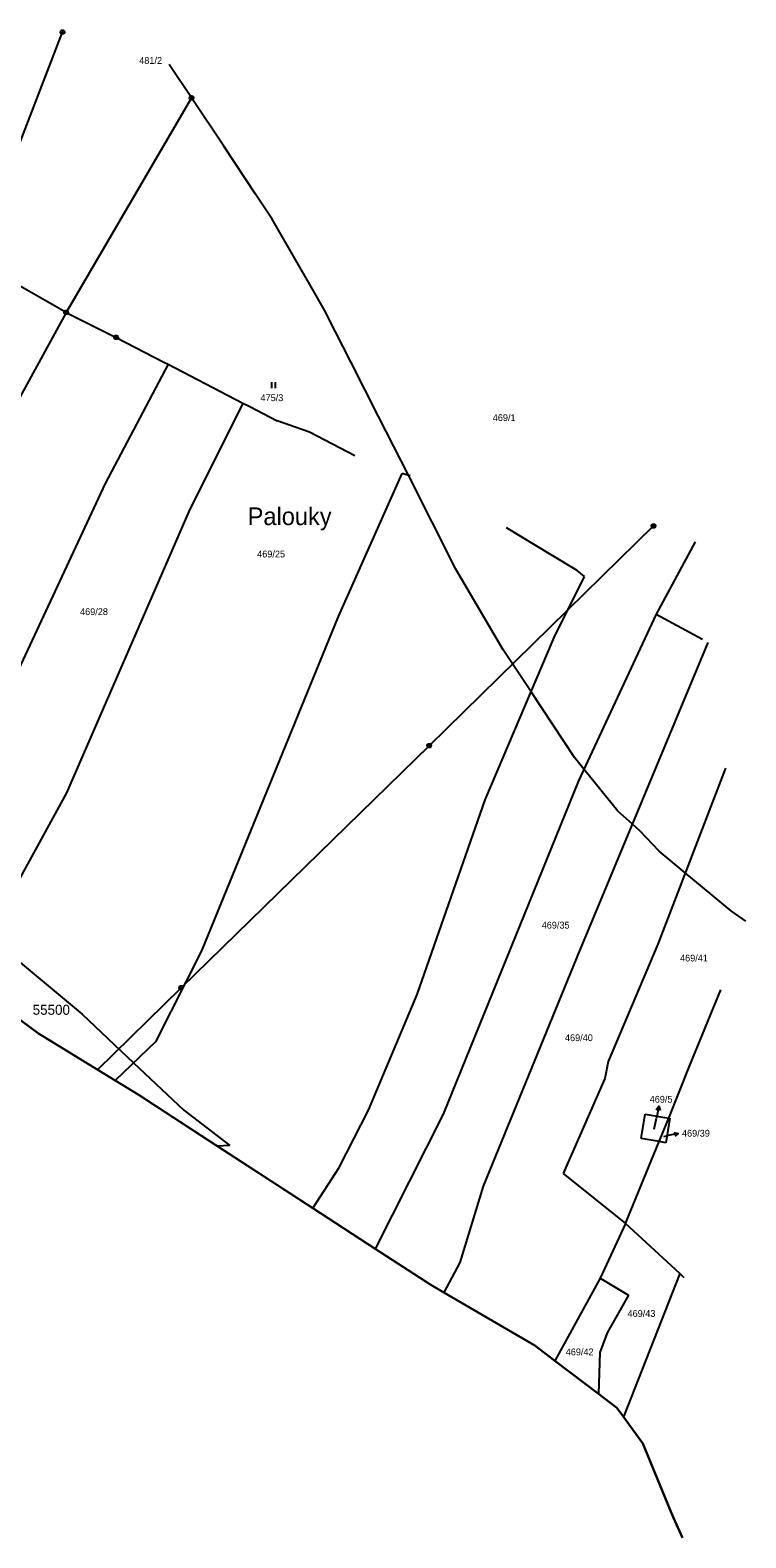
# Model space of a CAD drawing. Extents: x -755359 to -754474, y -1162585 to -1161655.
# Drawn here: x -754652.1 to -754473.6, y -1162087.8 to -1161711.6 of the extents above; entities that cross this region are included whole.
import ezdxf

# ---------------------------------------------------------------- set-up
doc = ezdxf.new("R2010")
doc.units = 0
for name, color, linetype in [('Vrstva 1', 7, 'Continuous'), ('Vrstva 11', 7, 'Continuous'), ('Vrstva 2', 7, 'Continuous'), ('Vrstva 3', 7, 'Continuous'), ('Vrstva 6', 7, 'Continuous'), ('Vrstva 7', 7, 'Continuous'), ('Vrstva 8', 7, 'Continuous')]:
    doc.layers.add(name, color=color, linetype=linetype)

msp = doc.modelspace()

# ---------------------------------------------------------------- linework, layer by layer
at = {"layer": 'Vrstva 1'}
for p, q in [((-754665.97, -1161769.03), (-754644.01, -1161712.08)), ((-754644.01, -1161712.08), (-754644.01, -1161712.08)), ((-754611.88, -1161728.5), (-754643.13, -1161782.03)), ((-754611.88, -1161728.5), (-754611.88, -1161728.5)), ((-754643.13, -1161782.03), (-754665.97, -1161769.03)), ((-754643.13, -1161782.03), (-754669.27, -1161829.84)), ((-754643.13, -1161782.03), (-754630.65, -1161788.28)), ((-754630.65, -1161788.28), (-754630.65, -1161788.28)), ((-754630.65, -1161788.28), (-754618.73, -1161794.45)), ((-754617.71, -1161794.98), (-754633.36, -1161824.71)), ((-754618.73, -1161794.45), (-754618.73, -1161794.45)), ((-754618.73, -1161794.45), (-754617.71, -1161794.98)), ((-754617.71, -1161794.98), (-754599.04, -1161804.66)), ((-754599.04, -1161804.66), (-754612.56, -1161831.72)), ((-754599.04, -1161804.66), (-754597.32, -1161805.55)), ((-754597.32, -1161805.55), (-754597.32, -1161805.55)), ((-754597.32, -1161805.55), (-754590.51, -1161809.08)), ((-754582.4, -1161811.93), (-754590.51, -1161809.08)), ((-754590.51, -1161809.08), (-754590.51, -1161809.08)), ((-754582.4, -1161811.93), (-754582.4, -1161811.93)), ((-754571.08, -1161817.79), (-754582.4, -1161811.93)), ((-754571.08, -1161817.79), (-754571.08, -1161817.79)), ((-754633.36, -1161824.71), (-754655.58, -1161872.43)), ((-754559.41, -1161822.27), (-754575.25, -1161857.88)), ((-754557.3, -1161822.8), (-754559.41, -1161822.27)), ((-754557.3, -1161822.8), (-754557.3, -1161822.8)), ((-754612.56, -1161831.72), (-754643, -1161901.95)), ((-754522.55, -1161842.29), (-754533.32, -1161835.8)), ((-754533.32, -1161835.8), (-754533.32, -1161835.8)), ((-754486.25, -1161839.25), (-754495.95, -1161857.32)), ((-754486.25, -1161839.25), (-754486.25, -1161839.25)), ((-754515.62, -1161846.48), (-754522.55, -1161842.29)), ((-754522.55, -1161842.29), (-754522.55, -1161842.29)), ((-754513.85, -1161847.95), (-754515.62, -1161846.48)), ((-754515.62, -1161846.48), (-754515.62, -1161846.48)), ((-754521.37, -1161863.15), (-754513.85, -1161847.95)), ((-754575.25, -1161857.88), (-754609.39, -1161941.34)), ((-754495.95, -1161857.32), (-754515.32, -1161898.89)), ((-754495.95, -1161857.32), (-754484.41, -1161863.55)), ((-754538.63, -1161903.69), (-754521.37, -1161863.15)), ((-754483.05, -1161864.39), (-754515.76, -1161942.9)), ((-754484.41, -1161863.55), (-754484.41, -1161863.55)), ((-754483.05, -1161864.39), (-754483.05, -1161864.39)), ((-754478.67, -1161895.77), (-754495.56, -1161939.67)), ((-754478.67, -1161895.77), (-754478.67, -1161895.77)), ((-754515.32, -1161898.89), (-754549.09, -1161982.12)), ((-754643, -1161901.95), (-754657.61, -1161928.54)), ((-754555.59, -1161952.23), (-754538.63, -1161903.69)), ((-754609.39, -1161941.34), (-754620.82, -1161964.09)), ((-754495.56, -1161939.67), (-754507.92, -1161969.01)), ((-754515.76, -1161942.9), (-754539.09, -1162000.11)), ((-754662.1, -1161953.11), (-754649.99, -1161962)), ((-754567.68, -1161981.15), (-754555.59, -1161952.23)), ((-754487.65, -1161970.13), (-754479.83, -1161951.12)), ((-754479.83, -1161951.12), (-754479.83, -1161951.12)), ((-754649.99, -1161962), (-754630.9, -1161973.72)), ((-754620.82, -1161964.09), (-754630.9, -1161973.72)), ((-754507.92, -1161969.01), (-754508.8, -1161973.21)), ((-754492.83, -1161983.08), (-754487.65, -1161970.13)), ((-754630.9, -1161973.72), (-754625.17, -1161977.24)), ((-754508.8, -1161973.21), (-754519.17, -1161996.94)), ((-754625.17, -1161977.24), (-754581.59, -1162005.57)), ((-754574.99, -1161995.43), (-754567.68, -1161981.15)), ((-754549.09, -1161982.12), (-754566.03, -1162015.68)), ((-754499.71, -1161988.2), (-754498.73, -1161982.13)), ((-754498.73, -1161982.13), (-754492.83, -1161983.08)), ((-754495.19, -1161988.97), (-754492.83, -1161983.08)), ((-754492.54, -1161983.13), (-754493.55, -1161989.25)), ((-754492.83, -1161983.08), (-754492.54, -1161983.13)), ((-754503.57, -1162009.41), (-754495.19, -1161988.97)), ((-754495.19, -1161988.97), (-754499.71, -1161988.2)), ((-754493.55, -1161989.25), (-754495.19, -1161988.97)), ((-754581.59, -1162005.57), (-754574.99, -1161995.43)), ((-754519.17, -1161996.94), (-754503.57, -1162009.41)), ((-754539.09, -1162000.11), (-754544.92, -1162019.1)), ((-754581.59, -1162005.57), (-754566.03, -1162015.68)), ((-754503.57, -1162009.41), (-754509.9, -1162023.04)), ((-754490.05, -1162021.88), (-754503.57, -1162009.41)), ((-754566.03, -1162015.68), (-754552.14, -1162024.71)), ((-754544.92, -1162019.1), (-754548.91, -1162026.6)), ((-754552.14, -1162024.71), (-754548.91, -1162026.6)), ((-754509.9, -1162023.04), (-754521.23, -1162043.66)), ((-754509.9, -1162023.04), (-754502.88, -1162027.26)), ((-754490.05, -1162021.88), (-754504.08, -1162057.68)), ((-754488.93, -1162022.92), (-754490.05, -1162021.88)), ((-754488.93, -1162022.92), (-754488.93, -1162022.92)), ((-754548.91, -1162026.6), (-754526.24, -1162039.85)), ((-754502.88, -1162027.26), (-754508.16, -1162036.68)), ((-754508.16, -1162036.68), (-754510.03, -1162041.56)), ((-754526.24, -1162039.85), (-754521.23, -1162043.66)), ((-754510.03, -1162041.56), (-754510.34, -1162051.93)), ((-754521.23, -1162043.66), (-754510.34, -1162051.93)), ((-754510.34, -1162051.93), (-754505.73, -1162055.42)), ((-754505.73, -1162055.42), (-754504.08, -1162057.68)), ((-754504.08, -1162057.68), (-754499.27, -1162064.28)), ((-754499.27, -1162064.28), (-754492.53, -1162080.68)), ((-754492.53, -1162080.68), (-754491.64, -1162082.85)), ((-754492.53, -1162080.68), (-754492.53, -1162080.68)), ((-754491.64, -1162082.85), (-754489.42, -1162087.84)), ((-754489.42, -1162087.84), (-754489.42, -1162087.84))]:
    msp.add_line(p, q, dxfattribs=at)
at = {"layer": 'Vrstva 11'}
for p, q in [((-754611.87, -1161728.48), (-754617.39, -1161720.16)), ((-754603.83, -1161740.58), (-754611.87, -1161728.48)), ((-754595.89, -1161752.54), (-754603.83, -1161740.58)), ((-754591.77, -1161758.73), (-754595.89, -1161752.54)), ((-754580.8, -1161777.83), (-754591.77, -1161758.73)), ((-754578.27, -1161782.24), (-754580.8, -1161777.83)), ((-754577.82, -1161783.11), (-754578.27, -1161782.24)), ((-754572.13, -1161794.35), (-754577.82, -1161783.11)), ((-754565.23, -1161807.97), (-754572.13, -1161794.35)), ((-754557.77, -1161822.68), (-754565.23, -1161807.97)), ((-754545.9, -1161846.11), (-754557.77, -1161822.68)), ((-754534.14, -1161866.25), (-754545.9, -1161846.11)), ((-754527.17, -1161876.76), (-754534.14, -1161866.25)), ((-754516.34, -1161893.09), (-754527.17, -1161876.76)), ((-754513.98, -1161896.01), (-754516.34, -1161893.09)), ((-754505.53, -1161906.48), (-754513.98, -1161896.01)), ((-754501.93, -1161909.7), (-754505.53, -1161906.48)), ((-754499.94, -1161911.48), (-754501.93, -1161909.7)), ((-754495.2, -1161916.49), (-754499.94, -1161911.48)), ((-754488.71, -1161921.88), (-754495.2, -1161916.49)), ((-754477.16, -1161931.47), (-754488.71, -1161921.88)), ((-754473.59, -1161933.93), (-754477.16, -1161931.47)), ((-754663.8, -1161936.61), (-754639.14, -1161957.17)), ((-754649.99, -1161962), (-754662.1, -1161953.11)), ((-754639.14, -1161957.17), (-754626.28, -1161969.31)), ((-754630.9, -1161973.72), (-754649.99, -1161962)), ((-754626.28, -1161969.31), (-754613.8, -1161981.1)), ((-754625.17, -1161977.24), (-754630.9, -1161973.72)), ((-754605.44, -1161990.07), (-754625.17, -1161977.24)), ((-754613.8, -1161981.1), (-754602.29, -1161989.95)), ((-754602.29, -1161989.95), (-754605.44, -1161990.07)), ((-754581.59, -1162005.57), (-754605.44, -1161990.07)), ((-754566.03, -1162015.68), (-754581.59, -1162005.57)), ((-754552.14, -1162024.71), (-754566.03, -1162015.68)), ((-754548.91, -1162026.6), (-754552.14, -1162024.71)), ((-754526.24, -1162039.85), (-754548.91, -1162026.6)), ((-754521.23, -1162043.66), (-754526.24, -1162039.85)), ((-754510.34, -1162051.93), (-754521.23, -1162043.66)), ((-754505.73, -1162055.42), (-754510.34, -1162051.93)), ((-754504.08, -1162057.68), (-754505.73, -1162055.42)), ((-754499.27, -1162064.28), (-754504.08, -1162057.68)), ((-754492.53, -1162080.68), (-754499.27, -1162064.28)), ((-754491.64, -1162082.85), (-754492.53, -1162080.68)), ((-754489.42, -1162087.84), (-754491.64, -1162082.85))]:
    msp.add_line(p, q, dxfattribs=at)
at = {"layer": 'Vrstva 3'}
for p, q in [((-754591.94, -1161799.43), (-754591.94, -1161800.93)), ((-754590.94, -1161800.93), (-754590.94, -1161799.43))]:
    msp.add_line(p, q, dxfattribs=at)
at = {"layer": 'Vrstva 6'}
for p, q in [((-754496.63, -1161835.32), (-754552.55, -1161890.16)), ((-754496.63, -1161835.32), (-754496.63, -1161835.32)), ((-754552.55, -1161890.16), (-754614.47, -1161950.58)), ((-754635.3, -1161971.03), (-754614.47, -1161950.58))]:
    msp.add_line(p, q, dxfattribs=at)
for points in [[(-754496.78, -1161834.84), (-754496.47, -1161834.84), (-754496.22, -1161835.02), (-754496.12, -1161835.31), (-754496.22, -1161835.6), (-754496.47, -1161835.78), (-754496.78, -1161835.78), (-754497.03, -1161835.6), (-754497.13, -1161835.31), (-754497.03, -1161835.02), (-754496.78, -1161834.84), (-754496.75, -1161834.88), (-754496.51, -1161834.88), (-754496.35, -1161834.96), (-754496.91, -1161834.96), (-754496.99, -1161835.04), (-754496.27, -1161835.04), (-754496.27, -1161835.12), (-754496.99, -1161835.12), (-754497.03, -1161835.2), (-754496.23, -1161835.2), (-754496.19, -1161835.28), (-754497.07, -1161835.28), (-754497.07, -1161835.36), (-754496.19, -1161835.36), (-754496.22, -1161835.44), (-754497.03, -1161835.44), (-754497.02, -1161835.52), (-754496.21, -1161835.52), (-754496.26, -1161835.6), (-754496.98, -1161835.6), (-754496.9, -1161835.68), (-754496.34, -1161835.68), (-754496.45, -1161835.76), (-754496.79, -1161835.76)], [(-754552.7, -1161889.68), (-754552.39, -1161889.68), (-754552.14, -1161889.86), (-754552.04, -1161890.15), (-754552.14, -1161890.44), (-754552.39, -1161890.62), (-754552.7, -1161890.62), (-754552.95, -1161890.44), (-754553.05, -1161890.15), (-754552.95, -1161889.86), (-754552.7, -1161889.68), (-754552.67, -1161889.72), (-754552.43, -1161889.72), (-754552.27, -1161889.8), (-754552.83, -1161889.8), (-754552.91, -1161889.88), (-754552.19, -1161889.88), (-754552.19, -1161889.96), (-754552.91, -1161889.96), (-754552.95, -1161890.04), (-754552.15, -1161890.04), (-754552.11, -1161890.12), (-754552.99, -1161890.12), (-754552.99, -1161890.2), (-754552.11, -1161890.2), (-754552.14, -1161890.28), (-754552.95, -1161890.28), (-754552.94, -1161890.36), (-754552.13, -1161890.36), (-754552.18, -1161890.44), (-754552.9, -1161890.44), (-754552.82, -1161890.52), (-754552.26, -1161890.52), (-754552.37, -1161890.6), (-754552.71, -1161890.6)], [(-754614.62, -1161950.1), (-754614.31, -1161950.1), (-754614.06, -1161950.28), (-754613.96, -1161950.57), (-754614.06, -1161950.86), (-754614.31, -1161951.04), (-754614.62, -1161951.04), (-754614.87, -1161950.86), (-754614.97, -1161950.57), (-754614.87, -1161950.28), (-754614.62, -1161950.1), (-754614.59, -1161950.14), (-754614.35, -1161950.14), (-754614.19, -1161950.22), (-754614.75, -1161950.22), (-754614.83, -1161950.3), (-754614.11, -1161950.3), (-754614.11, -1161950.38), (-754614.83, -1161950.38), (-754614.87, -1161950.46), (-754614.07, -1161950.46), (-754614.03, -1161950.54), (-754614.91, -1161950.54), (-754614.91, -1161950.62), (-754614.03, -1161950.62), (-754614.06, -1161950.7), (-754614.87, -1161950.7), (-754614.86, -1161950.78), (-754614.05, -1161950.78), (-754614.1, -1161950.86), (-754614.82, -1161950.86), (-754614.74, -1161950.94), (-754614.18, -1161950.94), (-754614.29, -1161951.02), (-754614.63, -1161951.02)]]:
    msp.add_lwpolyline(points, dxfattribs=at)
at = {"layer": 'Vrstva 7'}
for p, q in [((-754496.48, -1161985.84), (-754495.9, -1161983.08)), ((-754495.277, -1161980.145), (-754495.9, -1161983.08)), ((-754490.435, -1161986.949), (-754493.38, -1161987.52)), ((-754494.03, -1161987.65), (-754493.38, -1161987.52))]:
    msp.add_line(p, q, dxfattribs=at)
for points in [[(-754495.974, -1161981.02), (-754495.277, -1161980.145), (-754494.996, -1161981.227)], [(-754491.512, -1161986.648), (-754490.435, -1161986.949), (-754491.321, -1161987.63)]]:
    msp.add_lwpolyline(points, dxfattribs=at)
at = {"layer": 'Vrstva 8'}
for p, q in [((-754644.13, -1161712.08), (-754643.89, -1161712.08)), ((-754612, -1161728.5), (-754611.76, -1161728.5)), ((-754643.25, -1161782.03), (-754643.01, -1161782.03)), ((-754630.77, -1161788.28), (-754630.53, -1161788.28))]:
    msp.add_line(p, q, dxfattribs=at)
for points in [[(-754643.86, -1161711.6), (-754643.61, -1161711.78), (-754643.51, -1161712.07), (-754643.61, -1161712.36), (-754643.86, -1161712.54), (-754644.17, -1161712.54), (-754644.42, -1161712.36), (-754644.52, -1161712.07), (-754644.42, -1161711.78), (-754644.17, -1161711.6)], [(-754611.73, -1161728.02), (-754611.48, -1161728.2), (-754611.38, -1161728.49), (-754611.48, -1161728.78), (-754611.73, -1161728.96), (-754612.04, -1161728.96), (-754612.29, -1161728.78), (-754612.39, -1161728.49), (-754612.29, -1161728.2), (-754612.04, -1161728.02)], [(-754642.98, -1161781.55), (-754642.73, -1161781.73), (-754642.63, -1161782.02), (-754642.73, -1161782.31), (-754642.98, -1161782.49), (-754643.29, -1161782.49), (-754643.54, -1161782.31), (-754643.64, -1161782.02), (-754643.54, -1161781.73), (-754643.29, -1161781.55)], [(-754630.5, -1161787.8), (-754630.25, -1161787.98), (-754630.15, -1161788.27), (-754630.25, -1161788.56), (-754630.5, -1161788.74), (-754630.81, -1161788.74), (-754631.06, -1161788.56), (-754631.16, -1161788.27), (-754631.06, -1161787.98), (-754630.81, -1161787.8)]]:
    msp.add_lwpolyline(points, close=True, dxfattribs=at)

# ---------------------------------------------------------------- texts
at = {"layer": 'Vrstva 11'}
msp.add_text('55500', height=2.5, dxfattribs=at).set_placement((-754651.469, -1161957.31))
at = {"layer": 'Vrstva 2'}
for s, height, p in [('481/2', 1.7, (-754624.893, -1161720.02)), ('475/3', 1.7, (-754594.643, -1161804.18)), ('469/1', 1.7, (-754536.713, -1161809.15)), ('469/25', 1.7, (-754595.473, -1161843.18)), ('469/28', 1.7, (-754639.653, -1161857.57)), ('469/41', 1.7, (-754490.003, -1161944.01)), ('469/40', 1.7, (-754518.703, -1161963.89)), ('469/5', 0.1, (-754496.466, -1161985.84)), ('469/39', 0.1, (-754494.016, -1161987.65)), ('469/43', 1.7, (-754503.093, -1162032.7)), ('469/42', 1.7, (-754518.513, -1162042.29))]:
    msp.add_text(s, height=height, dxfattribs=at).set_placement(p)
at = {"layer": 'Vrstva 7'}
for s, height, p in [('Palouky', 4.4, (-754597.846, -1161835.11)), ('469/35', 1.7, (-754524.513, -1161935.8)), ('469/5', 1.7, (-754497.573, -1161979.25)), ('469/39', 1.7, (-754489.523, -1161987.73))]:
    msp.add_text(s, height=height, dxfattribs=at).set_placement(p)

doc.saveas('drawing.dxf')
